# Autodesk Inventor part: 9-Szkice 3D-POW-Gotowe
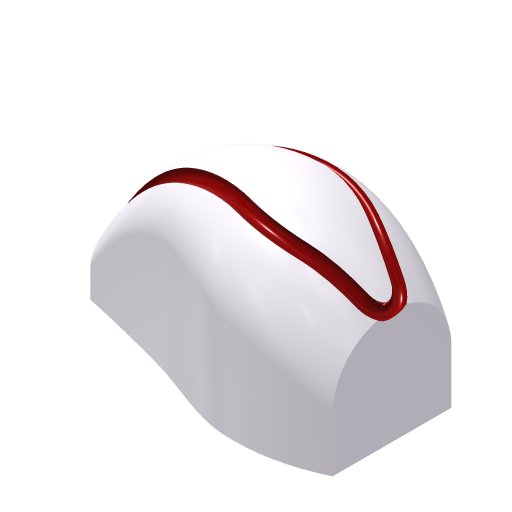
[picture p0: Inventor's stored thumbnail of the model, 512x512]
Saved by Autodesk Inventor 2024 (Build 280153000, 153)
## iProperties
Company: ATC
Created: 2023-03
Part Number: 9-Szkice 3D-POW-Gotowe
Document SubType Name: Modeling
Designer: Andrzej Jaskulski
Density: 1 g/cm^3
Material: Kurs-AJ
Appearance: Kurs-AJ
Checked By: A.J.
Engr Approved By: Andrzej Jaskulski
Mfg Approved By: Andrzej Jaskulski
Authority: A.J.
Title: A.J.: Kurs R2024-MEP
Author: Andrzej Jaskulski
Revision Number: 1/24
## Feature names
1. BAZA
2. ROWEK
## Parameters: d3 = 0, d4 = 90 deg, d5 = 0, d6 = 90 deg, d7 = 0, d8 = 90 deg, d9 = 0, d10 = 90 deg, d11 = 13 mm, d12 = 6 mm, d13 = 17 mm, d14 = 11 mm, d15 = 11 mm, d16 = 12 mm, d17 = 6 mm, d18 = 3 mm, d19 = 22 mm, d20 = 2 mm, d21 = 2 mm, d39 = 1.5 mm, d40 = 0, d41 = 0
